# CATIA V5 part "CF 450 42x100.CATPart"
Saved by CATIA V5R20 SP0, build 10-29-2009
Part number: CF 450 42x100
Definition: NONE
Nomenclature: CF 450 42x100
Source: Unknown
Description: CF 450 42x100
Bounding box of the stored display mesh (mm): x -31.5 to 31.5, y 0 to 100, z -31.5 to 31.5
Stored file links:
  C:\Users\Utente\Desktop\IO LAVORO\3D X SITO CF\X SITO\CF 450\CF 450 42x100.CATPart
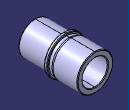
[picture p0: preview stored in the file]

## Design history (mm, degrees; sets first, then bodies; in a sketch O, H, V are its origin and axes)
Body1 "CF 450 42x100" (main body)
  Solid1: solid without history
